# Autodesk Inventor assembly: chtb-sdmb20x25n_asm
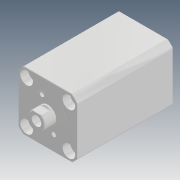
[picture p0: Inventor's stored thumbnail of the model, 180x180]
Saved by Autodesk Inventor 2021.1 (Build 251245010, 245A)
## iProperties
Company: Microsoft
Created: 2018-05
Part Number: chtb-sdmb20x25n_asm
Description: STEP AP214
Document SubType Name: Assembly
Designer: user
Title: chtb-sdmb20x25n_asm.STEP
Author: Windows
Revision Number: ÈÎºÎ
Sending System: SolidWorks 2015
Preprocessor: SwSTEP 2.0
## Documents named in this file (4)
- D:\Vault_2016\Projekty\Clamptek\Hydraulic\CHTB\CHTB-20\Inventor\CHTB-SDMB20x25N\chtb-sdmb20x25n_asm.iam
- D:\Vault_2016\Projekty\Clamptek\Hydraulic\CHTB\CHTB-20\Inventor\CHTB-SDMB20x25N\CHTB-SDMB20X25NBT.ipt
- D:\Vault_2016\Projekty\Clamptek\Hydraulic\CHTB\CHTB-20\Inventor\CHTB-SDMB20x25N\CHTB-SDMB20X25NHSG.ipt
- D:\Vault_2016\Projekty\Clamptek\Hydraulic\CHTB\CHTB-20\Inventor\CHTB-SDMB20x25N\QG_3.ipt
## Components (3 placed, 3 different names)
1. CHTB-SDMB20X25NBT_1
2. CHTB-SDMB20X25NHSG_2
3. QG_3_3
